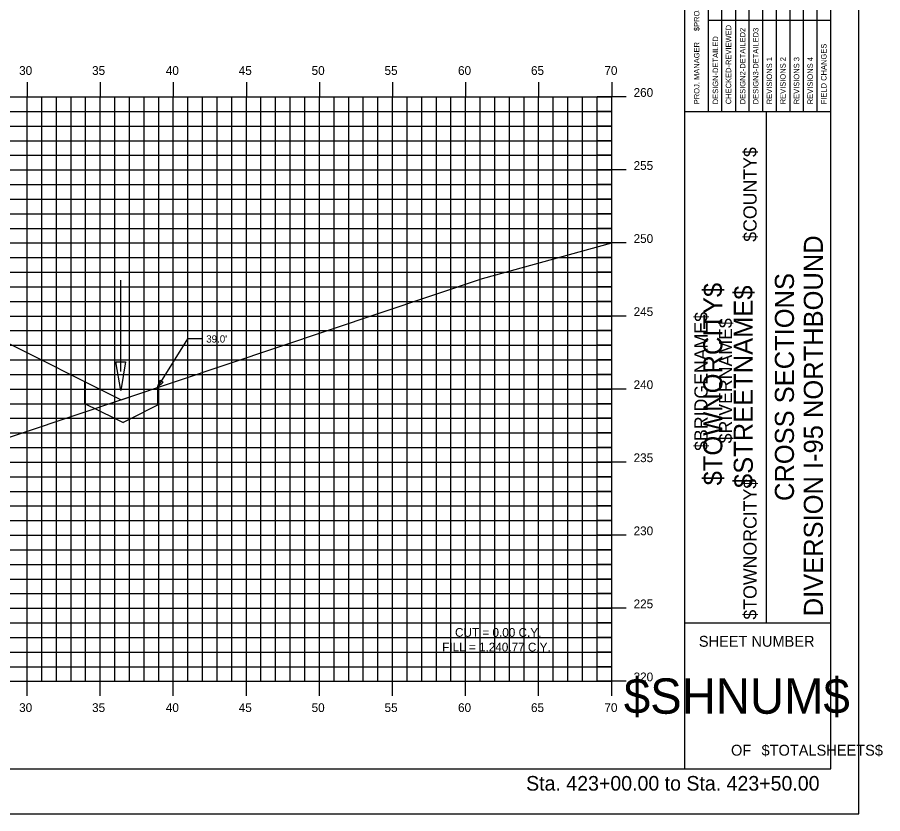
# Model space of a CAD drawing. Extents: x 1160718 to 1173142, y 616002 to 617630.
# Drawn here: x 1170213.5 to 1170272.7, y 616613.9 to 616668.4 of the extents above; entities that cross this region are included whole.
import ezdxf

# ---------------------------------------------------------------- set-up
doc = ezdxf.new("R2010")
doc.units = 0
for name, color, linetype in [('ANNOTATION', 7, 'Continuous'), ('BORDER', 7, 'Continuous'), ('BRIDGE_TITLE', 7, 'Continuous'), ('D_Drainage_Ditch_Line', 7, 'Continuous'), ('D_Roadway_SubGrade', 7, 'Continuous'), ('H_V ANNOTATION', 7, 'Continuous'), ('HIGHWAY_TITLE', 7, 'Continuous'), ('MAJOR', 7, 'Continuous'), ('MINOR', 7, 'Continuous'), ('PLOT BOUNDARY', 7, 'Continuous'), ('S_Roadway_Centerline', 7, 'Continuous')]:
    doc.layers.add(name, color=color, linetype=linetype)

msp = doc.modelspace()

# ---------------------------------------------------------------- linework, layer by layer
at = {"layer": 'ANNOTATION'}
for p in [(1170223.078, 616643.04), (1170226.151, 616646.359)]:
    msp.add_line(p, (1170225.151, 616646.359), dxfattribs=at)
for points in [[(1170218.078, 616643.452), (1170220.578, 616642.202), (1170223.078, 616643.04), (1170223.078, 616641.821), (1170221.078, 616640.821), (1170220.709, 616640.636)], [(1170218.078, 616643.452), (1170218.078, 616641.952), (1170220.078, 616640.952), (1170220.709, 616640.636)]]:
    msp.add_lwpolyline(points, dxfattribs=at)
msp.add_lwpolyline([(1170223.449, 616643.398), (1170223.078, 616643.04), (1170223.237, 616643.53)], close=True, dxfattribs=at)
at = {"layer": 'BORDER'}
for p, q in [((1170259.151, 616616.931), (1170259.151, 616721.931)), ((1170269.151, 616616.931), (1170269.151, 616721.931)), ((1170259.151, 616661.931), (1170269.151, 616661.931)), ((1170264.742, 616626.931), (1170264.742, 616661.931)), ((1170259.151, 616626.931), (1170269.151, 616626.931)), ((1170109.151, 616616.928), (1170269.151, 616616.928))]:
    msp.add_line(p, q, dxfattribs=at)
for points in [[(1170261.698, 616661.934), (1170261.698, 616679.431)], [(1170262.63, 616679.431), (1170262.63, 616661.934)], [(1170263.562, 616661.934), (1170263.562, 616679.431)], [(1170264.493, 616661.934), (1170264.493, 616679.431)], [(1170265.425, 616661.934), (1170265.425, 616679.431)], [(1170266.357, 616661.934), (1170266.357, 616679.431)], [(1170267.288, 616661.934), (1170267.288, 616679.431)], [(1170268.22, 616661.934), (1170268.22, 616679.431)], [(1170260.766, 616661.934), (1170260.766, 616678.725)], [(1170260.766, 616668.181), (1170269.151, 616668.181)]]:
    msp.add_lwpolyline(points, dxfattribs=at)
at = {"layer": 'D_Drainage_Ditch_Line'}
msp.add_line((1170220.555, 616644.134), (1170220.556, 616650.378), dxfattribs=at)
msp.add_lwpolyline([(1170220.227, 616644.791), (1170220.884, 616644.791), (1170220.555, 616642.822)], close=True, dxfattribs=at)
at = {"layer": 'D_Roadway_SubGrade'}
msp.add_line((1170204.151, 616650.415), (1170220.578, 616642.202), dxfattribs=at)
at = {"layer": 'MAJOR'}
for p, q in [((1170214.151, 616663.93), (1170214.151, 616662.928)), ((1170219.151, 616663.93), (1170219.151, 616662.928)), ((1170224.151, 616663.93), (1170224.151, 616662.928)), ((1170229.151, 616663.93), (1170229.151, 616662.928)), ((1170234.151, 616663.93), (1170234.151, 616662.928)), ((1170239.151, 616663.93), (1170239.151, 616662.928)), ((1170244.151, 616663.93), (1170244.151, 616662.928)), ((1170249.151, 616663.93), (1170249.151, 616662.928)), ((1170254.151, 616663.93), (1170254.151, 616662.928)), ((1170114.151, 616662.928), (1170254.151, 616662.928)), ((1170114.151, 616662.928), (1170254.151, 616662.928)), ((1170214.151, 616622.928), (1170214.151, 616662.928)), ((1170219.151, 616622.928), (1170219.151, 616662.928)), ((1170224.151, 616622.928), (1170224.151, 616662.928)), ((1170229.151, 616622.928), (1170229.151, 616662.928)), ((1170234.151, 616622.928), (1170234.151, 616662.928)), ((1170239.151, 616622.928), (1170239.151, 616662.928)), ((1170244.151, 616622.928), (1170244.151, 616662.928)), ((1170249.151, 616622.928), (1170249.151, 616662.928)), ((1170255.153, 616662.928), (1170253.149, 616662.928)), ((1170254.151, 616622.928), (1170254.151, 616662.928)), ((1170254.151, 616622.928), (1170254.151, 616662.928)), ((1170114.151, 616657.928), (1170254.151, 616657.928)), ((1170255.153, 616657.928), (1170253.149, 616657.928)), ((1170114.151, 616652.928), (1170254.151, 616652.928)), ((1170255.153, 616652.928), (1170253.149, 616652.928)), ((1170114.151, 616647.928), (1170254.151, 616647.928)), ((1170255.153, 616647.928), (1170253.149, 616647.928)), ((1170114.151, 616642.928), (1170254.151, 616642.928)), ((1170255.153, 616642.928), (1170253.149, 616642.928)), ((1170114.151, 616637.928), (1170254.151, 616637.928)), ((1170255.153, 616637.928), (1170253.149, 616637.928)), ((1170114.151, 616632.928), (1170254.151, 616632.928)), ((1170255.153, 616632.928), (1170253.149, 616632.928)), ((1170114.151, 616627.928), (1170254.151, 616627.928)), ((1170255.153, 616627.928), (1170253.149, 616627.928)), ((1170114.151, 616622.928), (1170254.151, 616622.928)), ((1170114.151, 616622.928), (1170254.151, 616622.928)), ((1170214.151, 616621.926), (1170214.151, 616622.928)), ((1170219.151, 616621.926), (1170219.151, 616622.928)), ((1170224.151, 616621.926), (1170224.151, 616622.928)), ((1170229.151, 616621.926), (1170229.151, 616622.928)), ((1170234.151, 616621.926), (1170234.151, 616622.928)), ((1170239.151, 616621.926), (1170239.151, 616622.928)), ((1170244.151, 616621.926), (1170244.151, 616622.928)), ((1170249.151, 616621.926), (1170249.151, 616622.928)), ((1170255.153, 616622.928), (1170253.149, 616622.928)), ((1170254.151, 616621.926), (1170254.151, 616622.928))]:
    msp.add_line(p, q, dxfattribs=at)
at = {"layer": 'MINOR'}
for p, q in [((1170215.151, 616622.928), (1170215.151, 616662.928)), ((1170216.151, 616622.928), (1170216.151, 616662.928)), ((1170217.151, 616622.928), (1170217.151, 616662.928)), ((1170218.151, 616622.928), (1170218.151, 616662.928)), ((1170220.151, 616622.928), (1170220.151, 616662.928)), ((1170221.151, 616622.928), (1170221.151, 616662.928)), ((1170222.151, 616622.928), (1170222.151, 616662.928)), ((1170223.151, 616622.928), (1170223.151, 616662.928)), ((1170225.151, 616622.928), (1170225.151, 616662.928)), ((1170226.151, 616622.928), (1170226.151, 616662.928)), ((1170227.151, 616622.928), (1170227.151, 616662.928)), ((1170228.151, 616622.928), (1170228.151, 616662.928)), ((1170230.151, 616622.928), (1170230.151, 616662.928)), ((1170231.151, 616622.928), (1170231.151, 616662.928)), ((1170232.151, 616622.928), (1170232.151, 616662.928)), ((1170233.151, 616622.928), (1170233.151, 616662.928)), ((1170235.151, 616622.928), (1170235.151, 616662.928)), ((1170236.151, 616622.928), (1170236.151, 616662.928)), ((1170237.151, 616622.928), (1170237.151, 616662.928)), ((1170238.151, 616622.928), (1170238.151, 616662.928)), ((1170240.151, 616622.928), (1170240.151, 616662.928)), ((1170241.151, 616622.928), (1170241.151, 616662.928)), ((1170242.151, 616622.928), (1170242.151, 616662.928)), ((1170243.151, 616622.928), (1170243.151, 616662.928)), ((1170245.151, 616622.928), (1170245.151, 616662.928)), ((1170246.151, 616622.928), (1170246.151, 616662.928)), ((1170247.151, 616622.928), (1170247.151, 616662.928)), ((1170248.151, 616622.928), (1170248.151, 616662.928)), ((1170250.151, 616622.928), (1170250.151, 616662.928)), ((1170251.151, 616622.928), (1170251.151, 616662.928)), ((1170252.151, 616622.928), (1170252.151, 616662.928)), ((1170253.151, 616622.928), (1170253.151, 616662.928)), ((1170114.151, 616661.928), (1170254.151, 616661.928)), ((1170254.151, 616661.928), (1170253.149, 616661.928)), ((1170114.151, 616660.928), (1170254.151, 616660.928)), ((1170254.151, 616660.928), (1170253.149, 616660.928)), ((1170114.151, 616659.928), (1170254.151, 616659.928)), ((1170254.151, 616659.928), (1170253.149, 616659.928)), ((1170114.151, 616658.928), (1170254.151, 616658.928)), ((1170254.151, 616658.928), (1170253.149, 616658.928)), ((1170114.151, 616656.928), (1170254.151, 616656.928)), ((1170254.151, 616656.928), (1170253.149, 616656.928)), ((1170114.151, 616655.928), (1170254.151, 616655.928)), ((1170254.151, 616655.928), (1170253.149, 616655.928)), ((1170114.151, 616654.928), (1170254.151, 616654.928)), ((1170254.151, 616654.928), (1170253.149, 616654.928)), ((1170114.151, 616653.928), (1170254.151, 616653.928)), ((1170254.151, 616653.928), (1170253.149, 616653.928)), ((1170114.151, 616651.928), (1170254.151, 616651.928)), ((1170254.151, 616651.928), (1170253.149, 616651.928)), ((1170114.151, 616650.928), (1170254.151, 616650.928)), ((1170254.151, 616650.928), (1170253.149, 616650.928)), ((1170114.151, 616649.928), (1170254.151, 616649.928)), ((1170254.151, 616649.928), (1170253.149, 616649.928)), ((1170114.151, 616648.928), (1170254.151, 616648.928)), ((1170254.151, 616648.928), (1170253.149, 616648.928)), ((1170114.151, 616646.928), (1170254.151, 616646.928)), ((1170254.151, 616646.928), (1170253.149, 616646.928)), ((1170114.151, 616645.928), (1170254.151, 616645.928)), ((1170254.151, 616645.928), (1170253.149, 616645.928)), ((1170114.151, 616644.928), (1170254.151, 616644.928)), ((1170254.151, 616644.928), (1170253.149, 616644.928)), ((1170114.151, 616643.928), (1170254.151, 616643.928)), ((1170254.151, 616643.928), (1170253.149, 616643.928)), ((1170114.151, 616641.928), (1170254.151, 616641.928)), ((1170254.151, 616641.928), (1170253.149, 616641.928)), ((1170114.151, 616640.928), (1170254.151, 616640.928)), ((1170254.151, 616640.928), (1170253.149, 616640.928)), ((1170114.151, 616639.928), (1170254.151, 616639.928)), ((1170254.151, 616639.928), (1170253.149, 616639.928)), ((1170114.151, 616638.928), (1170254.151, 616638.928)), ((1170254.151, 616638.928), (1170253.149, 616638.928)), ((1170114.151, 616636.928), (1170254.151, 616636.928)), ((1170254.151, 616636.928), (1170253.149, 616636.928)), ((1170114.151, 616635.928), (1170254.151, 616635.928)), ((1170254.151, 616635.928), (1170253.149, 616635.928)), ((1170114.151, 616634.928), (1170254.151, 616634.928)), ((1170254.151, 616634.928), (1170253.149, 616634.928)), ((1170114.151, 616633.928), (1170254.151, 616633.928)), ((1170254.151, 616633.928), (1170253.149, 616633.928)), ((1170114.151, 616631.928), (1170254.151, 616631.928)), ((1170254.151, 616631.928), (1170253.149, 616631.928)), ((1170114.151, 616630.928), (1170254.151, 616630.928)), ((1170254.151, 616630.928), (1170253.149, 616630.928)), ((1170114.151, 616629.928), (1170254.151, 616629.928)), ((1170254.151, 616629.928), (1170253.149, 616629.928)), ((1170114.151, 616628.928), (1170254.151, 616628.928)), ((1170254.151, 616628.928), (1170253.149, 616628.928)), ((1170114.151, 616626.928), (1170254.151, 616626.928)), ((1170254.151, 616626.928), (1170253.149, 616626.928)), ((1170114.151, 616625.928), (1170254.151, 616625.928)), ((1170254.151, 616625.928), (1170253.149, 616625.928)), ((1170114.151, 616624.928), (1170254.151, 616624.928)), ((1170254.151, 616624.928), (1170253.149, 616624.928)), ((1170114.151, 616623.928), (1170254.151, 616623.928)), ((1170254.151, 616623.928), (1170253.149, 616623.928))]:
    msp.add_line(p, q, dxfattribs=at)
at = {"layer": 'PLOT BOUNDARY'}
msp.add_lwpolyline([(1170101.057, 616613.869), (1170271.057, 616613.869), (1170271.057, 616723.869), (1170101.057, 616723.869)], close=True, dxfattribs=at)
at = {"layer": 'S_Roadway_Centerline'}
msp.add_lwpolyline([(1170114.151, 616654.034), (1170119.443, 616651.554), (1170130.924, 616646.199), (1170135.528, 616644.078), (1170163.591, 616632.625), (1170167.073, 616632.713), (1170181.848, 616633.572), (1170188.523, 616633.797), (1170199.794, 616635.233), (1170245.321, 616650.498), (1170254.151, 616652.947)], dxfattribs=at)

# ---------------------------------------------------------------- texts
at = {"layer": 'ANNOTATION'}
msp.add_text("39.0'", height=0.5, dxfattribs=at).set_placement((1170226.401, 616646.109))
for s, p in [('CUT = 0.00 C.Y.', (1170243.43, 616625.978)), ('FILL = 1,240.77 C.Y.', (1170242.551, 616624.977))]:
    msp.add_text(s, height=0.6, rotation=359.92408, dxfattribs=at).set_placement(p)
at = {"layer": 'BORDER'}
for s, height, rotation, p in [('$PROJMANAGER$', 0.37275, 90, (1170260.155, 616667.426)), ('CHECKED-REVIEWED', 0.37275, 90, (1170262.332, 616662.419)), ('DESIGN2-DETAILED2', 0.37275, 90, (1170263.301, 616662.419)), ('DESIGN3-DETAILED3', 0.37275, 90, (1170264.195, 616662.419)), ('PROJ. MANAGER', 0.37275, 90, (1170260.155, 616662.419)), ('DESIGN-DETAILED', 0.37275, 90, (1170261.437, 616662.419)), ('FIELD CHANGES', 0.37275, 90, (1170268.854, 616662.419)), ('REVISIONS 1', 0.37275, 90, (1170265.127, 616662.419)), ('REVISIONS 2', 0.37275, 90, (1170266.058, 616662.419)), ('REVISIONS 3', 0.37275, 90, (1170266.99, 616662.419)), ('REVISIONS 4', 0.37275, 90, (1170267.922, 616662.419)), ('DIVERSION I-95 NORTHBOUND  ', 1.30428, 90, (1170268.605, 616627.379)), ('CROSS SECTIONS', 1.30428, 90, (1170266.626, 616635.27)), ('SHEET NUMBER', 0.74527, 360, (1170260.116, 616625.295)), ('$SHNUM$', 2.4194, 360, (1170254.984, 616620.711)), ('OF', 0.7453, 360, (1170262.318, 616617.841)), ('$TOTALSHEETS$', 0.74527, 360, (1170264.407, 616617.841))]:
    msp.add_text(s, height=height, rotation=rotation, dxfattribs=at).set_placement(p)
at = {"layer": 'BRIDGE_TITLE'}
for s, height, p in [('$COUNTY$', 0.9072, (1170264.071, 616653.011)), ('$BRIDGENAME$', 0.90716, (1170260.717, 616638.7)), ('$RIVERNAME$', 0.90716, (1170262.394, 616639.214)), ('$TOWNORCITY$', 0.90716, (1170264.071, 616627.152))]:
    msp.add_text(s, height=height, rotation=90, dxfattribs=at).set_placement(p)
at = {"layer": 'H_V ANNOTATION'}
for s, height, p in [('30', 0.6, (1170213.599, 616664.428)), ('35', 0.6, (1170218.591, 616664.428)), ('40', 0.6, (1170223.637, 616664.428)), ('45', 0.6, (1170228.629, 616664.428)), ('50', 0.6, (1170233.615, 616664.428)), ('55', 0.6, (1170238.607, 616664.428)), ('60', 0.6, (1170243.637, 616664.428)), ('65', 0.6, (1170248.629, 616664.428)), ('70', 0.6, (1170253.653, 616664.428)), ('260', 0.6, (1170255.651, 616662.928)), ('255', 0.6, (1170255.651, 616657.928)), ('250', 0.6, (1170255.651, 616652.928)), ('245', 0.6, (1170255.651, 616647.928)), ('240', 0.6, (1170255.651, 616642.928)), ('235', 0.6, (1170255.651, 616637.928)), ('230', 0.6, (1170255.651, 616632.928)), ('225', 0.6, (1170255.651, 616627.928)), ('220', 0.6, (1170255.651, 616622.928)), ('30', 0.6, (1170213.599, 616620.828)), ('35', 0.6, (1170218.591, 616620.828)), ('40', 0.6, (1170223.637, 616620.828)), ('45', 0.6, (1170228.629, 616620.828)), ('50', 0.6, (1170233.615, 616620.828)), ('55', 0.6, (1170238.607, 616620.828)), ('60', 0.6, (1170243.637, 616620.828)), ('65', 0.6, (1170248.629, 616620.828)), ('70', 0.6, (1170253.653, 616620.828)), ('Sta. 423+00.00 to Sta. 423+50.00', 1.0002, (1170248.296, 616615.448))]:
    msp.add_text(s, height=height, dxfattribs=at).set_placement(p)
at = {"layer": 'HIGHWAY_TITLE'}
for s, p in [('$TOWNORCITY$', (1170261.723, 616636.34)), ('$STREETNAME$', (1170263.81, 616636.16))]:
    msp.add_text(s, height=1.30428, rotation=90, dxfattribs=at).set_placement(p)

doc.saveas('drawing.dxf')
